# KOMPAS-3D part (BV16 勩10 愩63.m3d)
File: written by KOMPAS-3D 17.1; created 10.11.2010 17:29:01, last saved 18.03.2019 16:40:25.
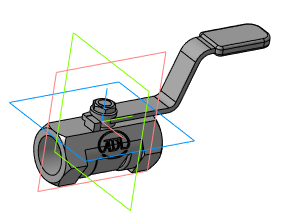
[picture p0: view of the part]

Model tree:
1. Плоскость XY
2. Плоскость ZX
3. Плоскость ZY
4. Ось X
5. Ось Y
6. Ось Z
7. Начало координат
8. Операция без истории:1

Referenced files in \\adlc.lan\data\АДЛ_ПКД\3D-модели\ADL production\Краны шаровые серии BV\BV16\KOMPAS 3D\: шаровый кран BV16 Ду15.a3d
